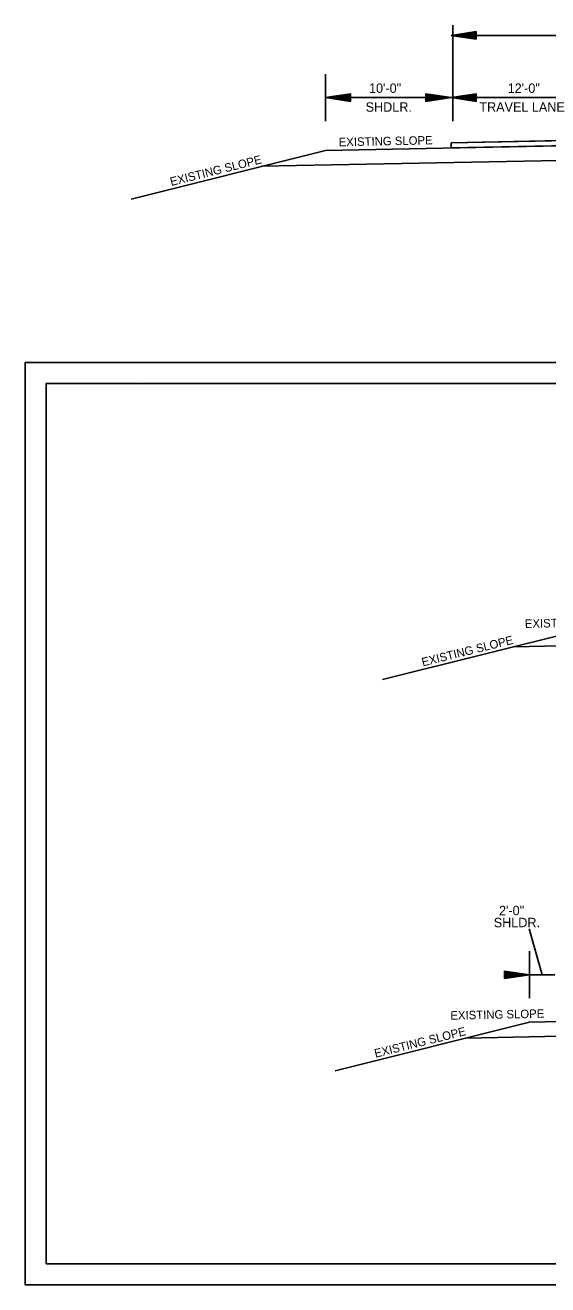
# Model space of a CAD drawing. Extents: x 34757 to 38214, y 51436 to 59430.
# Drawn here: x 34757 to 35381, y 56770 to 58272 of the extents above; entities that cross this region are included whole.
import ezdxf

# ---------------------------------------------------------------- set-up
doc = ezdxf.new("R2010")
doc.units = 0
for name, color, linetype in [('Default', 7, 'Continuous'), ('DSN_DRFT_Junk-No-Plot', 7, 'Continuous'), ('SHET_Border-Lines', 7, 'Continuous')]:
    doc.layers.add(name, color=color, linetype=linetype)

msp = doc.modelspace()

# ---------------------------------------------------------------- linework, layer by layer
at = {"layer": 'Default'}
for p, q in [((35295, 58264.4), (35265, 58259.9)), ((35267, 58157.6), (35267, 58272)), ((35295, 58255.4), (35295, 58264.4)), ((35985, 58259.9), (35265, 58259.9)), ((35295, 58255.4), (35265, 58259.9)), ((35295, 58263.6), (35270, 58259.9)), ((35295, 58256.1), (35270, 58259.9)), ((35295, 58262.9), (35275.2, 58259.9)), ((35295, 58256.9), (35275.2, 58259.9)), ((35295, 58262.1), (35280.2, 58259.9)), ((35295, 58257.7), (35280.2, 58259.9)), ((35295, 58261.4), (35285.3, 58259.9)), ((35295, 58258.4), (35285.3, 58259.9)), ((35295, 58260.6), (35290.3, 58259.9)), ((35295, 58259.2), (35290.3, 58259.9)), ((35115, 58157.6), (35115, 58213.6)), ((35145, 58190.1), (35115, 58185.6)), ((35145, 58189.4), (35120, 58185.6)), ((35145, 58188.6), (35125.2, 58185.6)), ((35145, 58181.1), (35145, 58190.1)), ((35235, 58190.1), (35265, 58185.6)), ((35235, 58190.1), (35235, 58181.1)), ((35235, 58189.4), (35260, 58185.6)), ((35235, 58188.6), (35254.8, 58185.6)), ((35295, 58190.1), (35265, 58185.6)), ((35295, 58189.4), (35270, 58185.6)), ((35295, 58188.6), (35275.2, 58185.6)), ((35295, 58181.1), (35295, 58190.1)), ((35265, 58185.6), (35115, 58185.6)), ((35145, 58181.1), (35115, 58185.6)), ((35145, 58181.9), (35120, 58185.6)), ((35145, 58182.6), (35125.2, 58185.6)), ((35145, 58187.9), (35130.2, 58185.6)), ((35145, 58183.4), (35130.2, 58185.6)), ((35145, 58187.1), (35135.3, 58185.6)), ((35145, 58184.2), (35135.3, 58185.6)), ((35145, 58186.3), (35140.3, 58185.6)), ((35145, 58184.9), (35140.3, 58185.6)), ((35235, 58187.9), (35249.9, 58185.6)), ((35235, 58187.1), (35244.8, 58185.6)), ((35235, 58186.3), (35239.8, 58185.6)), ((35235, 58181.1), (35265, 58185.6)), ((35235, 58184.2), (35244.8, 58185.6)), ((35235, 58182.6), (35254.8, 58185.6)), ((35235, 58181.9), (35260, 58185.6)), ((35235, 58183.4), (35249.9, 58185.6)), ((35235, 58184.9), (35239.8, 58185.6)), ((35445, 58185.6), (35265, 58185.6)), ((35295, 58181.1), (35265, 58185.6)), ((35295, 58181.9), (35270, 58185.6)), ((35295, 58182.6), (35275.2, 58185.6)), ((35295, 58187.9), (35280.2, 58185.6)), ((35295, 58183.4), (35280.2, 58185.6)), ((35295, 58187.1), (35285.3, 58185.6)), ((35295, 58184.2), (35285.3, 58185.6)), ((35295, 58186.3), (35290.3, 58185.6)), ((35295, 58184.9), (35290.3, 58185.6)), ((35625, 58132.9), (35115, 58122.7)), ((35625, 58138.9), (35265, 58131.7)), ((35265, 58131.7), (35265, 58125.7)), ((35115, 58122.7), (34883, 58064.7)), ((35625, 58115.4), (35038.9, 58103.7)), ((35415.3, 57549.6), (35183.3, 57491.6)), ((35625.3, 57536.3), (35339.2, 57530.6)), ((35373.8, 57139.4), (35358.4, 57194.1)), ((35358.8, 57111.4), (35358.8, 57167.4)), ((35328.8, 57143.9), (35358.8, 57139.4)), ((35328.8, 57143.9), (35328.8, 57134.9)), ((35328.8, 57143.2), (35353.8, 57139.4)), ((35328.8, 57142.4), (35348.6, 57139.4)), ((35328.8, 57141.6), (35343.6, 57139.4)), ((35328.8, 57140.9), (35338.6, 57139.4)), ((35328.8, 57140.1), (35333.5, 57139.4)), ((35328.8, 57134.9), (35358.8, 57139.4)), ((35328.8, 57137.9), (35338.6, 57139.4)), ((35328.8, 57136.4), (35348.6, 57139.4)), ((35328.8, 57135.7), (35353.8, 57139.4)), ((35328.8, 57137.2), (35343.6, 57139.4)), ((35328.8, 57138.7), (35333.5, 57139.4)), ((35388.8, 57139.4), (35358.8, 57139.4)), ((35358.8, 57082.9), (35126.8, 57024.9)), ((35546.3, 57086.7), (35358.8, 57082.9)), ((35546.3, 57069.2), (35282.7, 57063.9))]:
    msp.add_line(p, q, dxfattribs=at)
for points in [[(35265, 58131.7), (35265, 58125.7), (35625, 58132.9), (35985, 58125.7), (35985, 58131.7), (35625, 58138.9)], [(34756.6, 57869.6), (34756.6, 56769.6), (36456.6, 56769.6), (36456.6, 57869.6)]]:
    msp.add_lwpolyline(points, close=True, dxfattribs=at)
at = {"layer": 'DSN_DRFT_Junk-No-Plot'}
msp.add_lwpolyline([(34756.6, 57869.6), (34756.6, 56769.6), (36456.6, 56769.6), (36456.6, 57869.6)], close=True, dxfattribs=at)
at = {"layer": 'SHET_Border-Lines'}
msp.add_line((34897.7, 57848.2), (34897.7, 57848.2), dxfattribs=at)
msp.add_line((34897.7, 57848.2), (34897.7, 57848.2), dxfattribs=at)
for points in [[(34756.6, 56769.6), (36456.6, 56769.6), (36456.6, 57869.6), (34756.6, 57869.6)], [(34781.6, 56794.6), (36431.6, 56794.6), (36431.6, 57844.6), (34781.6, 57844.6)]]:
    msp.add_lwpolyline(points, close=True, dxfattribs=at)

# ---------------------------------------------------------------- texts
at = {"layer": 'Default'}
for s, p in [('10\'-0"', (35167.1, 58191.3)), ('12\'-0"', (35332.6, 58191.3)), ('SHDLR.', (35163.1, 58168.8)), ('TRAVEL LANE', (35298.8, 58168.8)), ('2\'-0"', (35322.3, 57210.4)), ('SHLDR.', (35316, 57196.1))]:
    msp.add_text(s, height=11.25, dxfattribs=at).set_placement(p)
for rotation, p in [(1.2244, (35131, 58127.5)), (14.0368, (34931, 58080.2)), (1.2244, (35353.2, 57553.1)), (14.0368, (35231.3, 57507.1)), (1.2244, (35264.3, 57085.8)), (14.0368, (35174.8, 57040.4))]:
    msp.add_text('EXISTING SLOPE', height=10.125, rotation=rotation, dxfattribs=at).set_placement(p)

doc.saveas('drawing.dxf')
